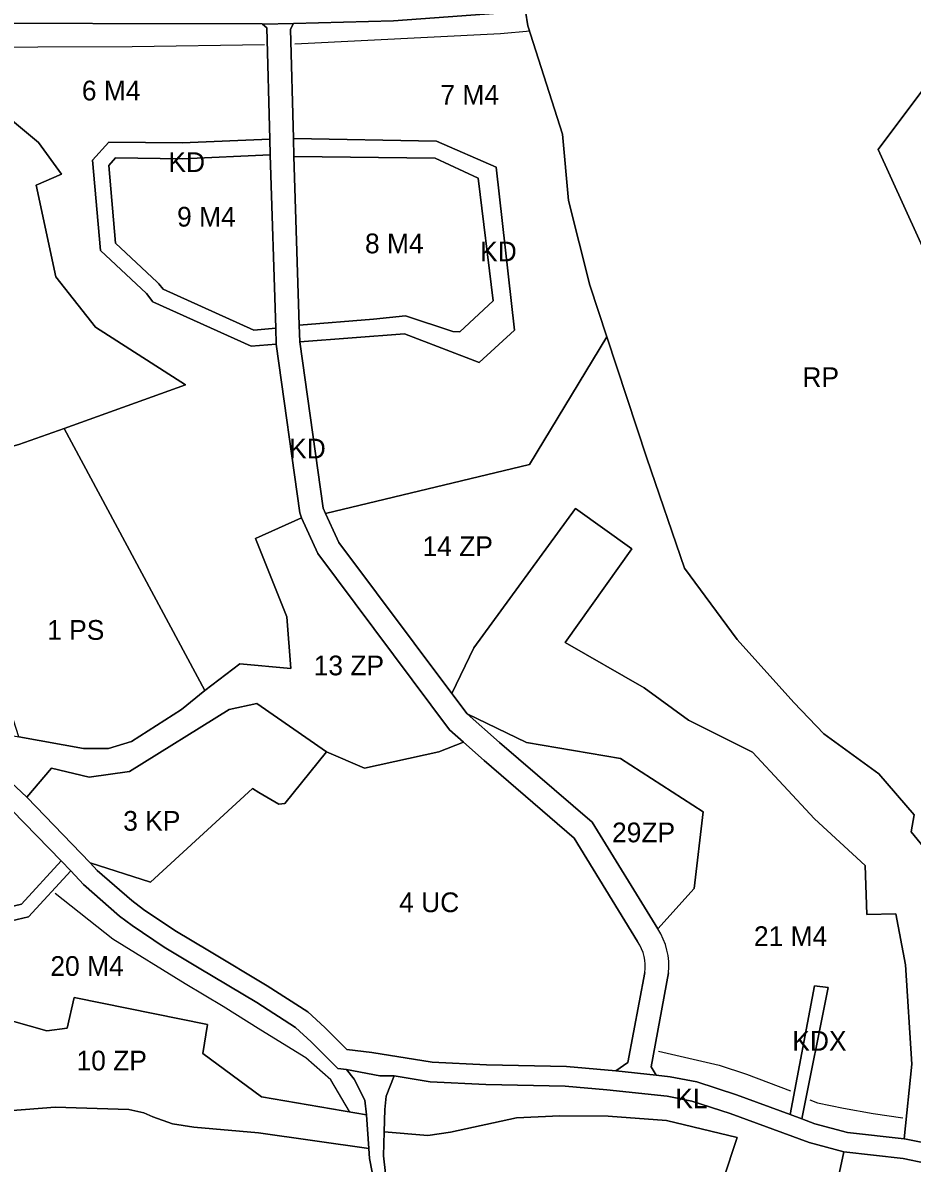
# Model space of a CAD drawing. Extents: x 7437831 to 7440315, y 5545798 to 5547888.
# Drawn here: x 7438934 to 7439385, y 5546989 to 5547567 of the extents above; entities that cross this region are included whole.
import ezdxf

# ---------------------------------------------------------------- set-up
doc = ezdxf.new("R2010")
doc.units = 0
for name, color, linetype in [('linie_rozgraniczajace', 7, 'Continuous'), ('linie_zabudowy_nieprzekraczalne', 7, 'Continuous'), ('oznaczenia_przeznaczen', 7, 'Continuous')]:
    doc.layers.add(name, color=color, linetype=linetype)

msp = doc.modelspace()

# ---------------------------------------------------------------- linework, layer by layer
at = {"layer": 'linie_rozgraniczajace'}
for points in [[(7439380.63, 5547586.73), (7439395.54, 5547573.5), (7439398.38, 5547559.18), (7439402.31, 5547543.75), (7439391.54, 5547533.89), (7439367.76, 5547502.29), (7439407.73, 5547414.82), (7439556.07, 5547232.92), (7439403.12, 5547142.44), (7439397.35, 5547140.99), (7439384.59, 5547156.64), (7439386.01, 5547165.4), (7439368.08, 5547186.09), (7439340.2, 5547206.42), (7439325.09, 5547222.17), (7439296.32, 5547254.08), (7439269.71, 5547290.21), (7439250.62, 5547346.08), (7439230.35, 5547407.55), (7439221.74, 5547433.66), (7439210.84, 5547476.54), (7439207.87, 5547510.17), (7439190.23, 5547565.03), (7439189.02, 5547572.47)], [(7439189.02, 5547572.47), (7439190.23, 5547565.03), (7439207.87, 5547510.17), (7439210.84, 5547476.54), (7439221.74, 5547433.66), (7439230.35, 5547407.55), (7439191.09, 5547342.82), (7439087.77, 5547317.91), (7439086.54, 5547320.63), (7439074.71, 5547404.92), (7439127.76, 5547409.05), (7439165.53, 5547394.42), (7439183.56, 5547410.93), (7439174.29, 5547493.48), (7439143.9, 5547506.62), (7439071.47, 5547507.9), (7439070.05, 5547563.26), (7439071.56, 5547566.23), (7439122.23, 5547567.49)], [(7438828.96, 5547566.29), (7438858.2, 5547566.45), (7438883.67, 5547566.33), (7438889.93, 5547556.37), (7438911.91, 5547531.01), (7438942.2, 5547505.98), (7438953.96, 5547489.8), (7438941.06, 5547484.22), (7438951.02, 5547437.82), (7438971.24, 5547412.38), (7439016.84, 5547383.23), (7438955.2, 5547361.08), (7438932.28, 5547352.94), (7438898.23, 5547343.32), (7438865.97, 5547445.48), (7438855.72, 5547499.1), (7438851.23, 5547513.66), (7438841.19, 5547535.01), (7438823.53, 5547527.36), (7438809.33, 5547551.21), (7438805.74, 5547563.28), (7438810.97, 5547564.3), (7438816.19, 5547565.31)], [(7439402.31, 5547543.75), (7439404.34, 5547535.78), (7439410.65, 5547514.06), (7439420.51, 5547489.6), (7439431.75, 5547471.05), (7439450.29, 5547445.41), (7439476.68, 5547412.41), (7439521.84, 5547350.29), (7439537.42, 5547327.35), (7439572.92, 5547278.45), (7439587.97, 5547258.66), (7439592.45, 5547251.78), (7439556.07, 5547232.92), (7439407.73, 5547414.82), (7439367.76, 5547502.29), (7439391.54, 5547533.89)], [(7439062.76, 5547403.81), (7439050.03, 5547402.66), (7439000.29, 5547425.19), (7438996.99, 5547429.39), (7438973.64, 5547451.23), (7438969.66, 5547497.02), (7438977.84, 5547506.11), (7439015.15, 5547505.71), (7439059.47, 5547507.6), (7439059.73, 5547499.6), (7439015.27, 5547497.71), (7438981.37, 5547498.07), (7438977.93, 5547494.25), (7438981.34, 5547454.97), (7439002.45, 5547435.23), (7439003.28, 5547434.33), (7439005.37, 5547431.67), (7439051.41, 5547410.81), (7439062.51, 5547411.8)], [(7439071.47, 5547507.9), (7439143.9, 5547506.62), (7439174.29, 5547493.48), (7439183.56, 5547410.93), (7439165.53, 5547394.42), (7439127.76, 5547409.05), (7439074.71, 5547404.92), (7439074.45, 5547413.34), (7439112.1, 5547416.37), (7439128.21, 5547418.04), (7439152.32, 5547410.11), (7439155.72, 5547409.99), (7439172.76, 5547425.7), (7439165.09, 5547487.89), (7439143.32, 5547497.95), (7439071.75, 5547498.86)], [(7439062.51, 5547411.8), (7439051.41, 5547410.81), (7439005.37, 5547431.67), (7439003.28, 5547434.33), (7439002.45, 5547435.23), (7438981.34, 5547454.97), (7438977.93, 5547494.25), (7438981.37, 5547498.07), (7439015.27, 5547497.71), (7439059.73, 5547499.6)], [(7439071.75, 5547498.86), (7439143.32, 5547497.95), (7439165.09, 5547487.89), (7439172.76, 5547425.7), (7439155.72, 5547409.99), (7439152.32, 5547410.11), (7439128.21, 5547418.04), (7439112.1, 5547416.37), (7439074.45, 5547413.34)], [(7438955.2, 5547361.08), (7439026.61, 5547228.25), (7439014.66, 5547218.74), (7438989.33, 5547202.5), (7438977.77, 5547198.98), (7438965.14, 5547198.94), (7438932.24, 5547204.92), (7438888.7, 5547340.63), (7438898.23, 5547343.32), (7438932.28, 5547352.94)], [(7439075.64, 5547315.72), (7439083.79, 5547297.7), (7439150.54, 5547208.32), (7439157.59, 5547202.13), (7439145.18, 5547197.27), (7439107.47, 5547188.91), (7439088.31, 5547197.19), (7439052.98, 5547221.74), (7439038.94, 5547218.77), (7438988.47, 5547187.22), (7438967.95, 5547184.39), (7438948.84, 5547188.98), (7438936.39, 5547174.36), (7438896.31, 5547211.65), (7438932.24, 5547204.92), (7438965.14, 5547198.94), (7438977.77, 5547198.98), (7438989.33, 5547202.5), (7439014.66, 5547218.74), (7439026.61, 5547228.25), (7439044.3, 5547241.89), (7439070.18, 5547239.54), (7439068.06, 5547265.64), (7439052.3, 5547305.33)], [(7438809.04, 5547223.28), (7438841.11, 5547194.03), (7438847.73, 5547185.6), (7438883.2, 5547212.78), (7438893.1, 5547200.63), (7438912.87, 5547182.74), (7438922.54, 5547173.99), (7438953.8, 5547142.07), (7438933.7, 5547120.16), (7438915.71, 5547115.81), (7438884.23, 5547111.26), (7438805.66, 5547070.29), (7438746.38, 5547044.16), (7438704.39, 5547030.75), (7438652.23, 5547099.85), (7438735.45, 5547165.35), (7438790.4, 5547208.6)], [(7438936.39, 5547174.36), (7438948.84, 5547188.98), (7438967.95, 5547184.39), (7438988.47, 5547187.22), (7439038.94, 5547218.77), (7439052.98, 5547221.74), (7439088.31, 5547197.19), (7439067.17, 5547171.08), (7439064, 5547170.71), (7439053.99, 5547176.68), (7439050.68, 5547178.66), (7438998.97, 5547131.16), (7438968.45, 5547141.03)], [(7439159.47, 5547216.45), (7439189.56, 5547202.03), (7439237.18, 5547193.81), (7439279.09, 5547166.79), (7439274.62, 5547127.96), (7439256.06, 5547107.5), (7439222.82, 5547161.54), (7439175.92, 5547201.99)], [(7439323.23, 5547013.51), (7439335.61, 5547078.66), (7439342.39, 5547077.83), (7439329.17, 5547011.32)]]:
    msp.add_lwpolyline(points, close=True, dxfattribs=at)
for points in [[(7439189.02, 5547572.47), (7439122.23, 5547567.49), (7439071.56, 5547566.23)], [(7439055.78, 5547565.86), (7439055.68, 5547565.95), (7438883.67, 5547566.33)], [(7438883.67, 5547566.33), (7439055.68, 5547565.95), (7439055.78, 5547565.86), (7439058.03, 5547563.99), (7439059.47, 5547507.6), (7439015.15, 5547505.71), (7438977.84, 5547506.11), (7438969.66, 5547497.02), (7438973.64, 5547451.23), (7438996.99, 5547429.39), (7439000.29, 5547425.19), (7439050.03, 5547402.66), (7439062.76, 5547403.81), (7439074.75, 5547318.29), (7439075.64, 5547315.72), (7439052.3, 5547305.33), (7439068.06, 5547265.64), (7439070.18, 5547239.54), (7439044.3, 5547241.89), (7439026.61, 5547228.25), (7438955.2, 5547361.08), (7439016.84, 5547383.23), (7438971.24, 5547412.38), (7438951.02, 5547437.82), (7438941.06, 5547484.22), (7438953.96, 5547489.8), (7438942.2, 5547505.98), (7438911.91, 5547531.01)], [(7439071.56, 5547566.23), (7439055.78, 5547565.86)], [(7439055.78, 5547565.86), (7439071.56, 5547566.23), (7439070.05, 5547563.26)], [(7439059.47, 5547507.6), (7439058.03, 5547563.99), (7439055.78, 5547565.86)], [(7439070.05, 5547563.26), (7439071.47, 5547507.9), (7439071.75, 5547498.86), (7439074.45, 5547413.34), (7439074.71, 5547404.92), (7439086.54, 5547320.63), (7439087.77, 5547317.91)], [(7439059.73, 5547499.6), (7439059.47, 5547507.6)], [(7439062.51, 5547411.8), (7439059.73, 5547499.6)], [(7439062.76, 5547403.81), (7439062.51, 5547411.8)], [(7439393.87, 5546998.67), (7439382.07, 5547001.08), (7439381.03, 5547001.2), (7439384.83, 5547039.06), (7439381.68, 5547089.27), (7439376.83, 5547115.26), (7439362.11, 5547114.77), (7439361.24, 5547139.74), (7439335.55, 5547163.34), (7439304.11, 5547197.02), (7439271.63, 5547213.34), (7439249.2, 5547229.62), (7439209.21, 5547252.55), (7439242.97, 5547300.1), (7439214.5, 5547320.47), (7439162.9, 5547249.87), (7439151.74, 5547226.79), (7439094.56, 5547303.33), (7439093.56, 5547305.16), (7439087.77, 5547317.91), (7439191.09, 5547342.82), (7439230.35, 5547407.55), (7439250.62, 5547346.08), (7439269.71, 5547290.21), (7439296.32, 5547254.08), (7439325.09, 5547222.17), (7439340.2, 5547206.42), (7439368.08, 5547186.09), (7439386.01, 5547165.4), (7439384.59, 5547156.64), (7439397.35, 5547140.99)], [(7439083.79, 5547297.7), (7439075.64, 5547315.72), (7439074.75, 5547318.29), (7439062.76, 5547403.81)], [(7439087.77, 5547317.91), (7439093.56, 5547305.16)], [(7439151.74, 5547226.79), (7439162.9, 5547249.87), (7439214.5, 5547320.47), (7439242.97, 5547300.1), (7439209.21, 5547252.55), (7439249.2, 5547229.62), (7439271.63, 5547213.34), (7439304.11, 5547197.02), (7439335.55, 5547163.34), (7439361.24, 5547139.74), (7439362.11, 5547114.77), (7439376.83, 5547115.26), (7439381.68, 5547089.27), (7439384.83, 5547039.06), (7439381.03, 5547001.2), (7439352.25, 5547004.45), (7439335.79, 5547008.87), (7439329.17, 5547011.32), (7439342.39, 5547077.83), (7439335.61, 5547078.66), (7439323.23, 5547013.51)], [(7439093.56, 5547305.16), (7439094.56, 5547303.33), (7439151.74, 5547226.79), (7439159.47, 5547216.45), (7439175.92, 5547201.99), (7439222.82, 5547161.54), (7439256.06, 5547107.5)], [(7439157.59, 5547202.13), (7439150.54, 5547208.32), (7439083.79, 5547297.7)], [(7439159.47, 5547216.45), (7439151.74, 5547226.79)], [(7439256.06, 5547107.5), (7439274.62, 5547127.96), (7439279.09, 5547166.79), (7439237.18, 5547193.81), (7439189.56, 5547202.03), (7439159.47, 5547216.45)], [(7438896.31, 5547211.65), (7438936.39, 5547174.36), (7438968.45, 5547141.03), (7438972.06, 5547137.15), (7438989.55, 5547121.86), (7438995.53, 5547117.4), (7439011.31, 5547106.7), (7439028.89, 5547096.29), (7439058.19, 5547078.79), (7439078.73, 5547065.47), (7439087.3, 5547057.66), (7439098.57, 5547046.41), (7439111.22, 5547044.95), (7439141.81, 5547040.11), (7439169.29, 5547038.7), (7439209.79, 5547037.88), (7439234.79, 5547035.73), (7439255.34, 5547033.45), (7439262.44, 5547032.69), (7439275.95, 5547030.01), (7439296.05, 5547023.53), (7439323.23, 5547013.51), (7439329.17, 5547011.32), (7439335.79, 5547008.87), (7439352.25, 5547004.45), (7439381.03, 5547001.2), (7439382.07, 5547001.08), (7439393.87, 5546998.67)], [(7439088.31, 5547197.19), (7439107.47, 5547188.91), (7439145.18, 5547197.27), (7439157.59, 5547202.13)], [(7439168.09, 5547192.91), (7439157.59, 5547202.13)], [(7439157.59, 5547202.13), (7439168.09, 5547192.91), (7439213.69, 5547153.57), (7439245.9, 5547101.1)], [(7439067.17, 5547171.08), (7439088.31, 5547197.19)], [(7439245.9, 5547101.1), (7439213.69, 5547153.57), (7439168.09, 5547192.91)], [(7439122.44, 5547033.05), (7439115.22, 5547033.09), (7439098.29, 5547036.37), (7439093.96, 5547036.87), (7439080.4, 5547050.42), (7439072.6, 5547057.52), (7439052.9, 5547070.3), (7439023.78, 5547087.7), (7439005.95, 5547098.26), (7438989.74, 5547109.25), (7438983.26, 5547114.08), (7438965.09, 5547129.96), (7438958.59, 5547136.94), (7438953.8, 5547142.07), (7438922.54, 5547173.99)], [(7438968.45, 5547141.03), (7438998.97, 5547131.16), (7439050.68, 5547178.66), (7439053.99, 5547176.68)], [(7439053.99, 5547176.68), (7439064, 5547170.71)], [(7439064, 5547170.71), (7439067.17, 5547171.08)], [(7438652.23, 5547099.85), (7438704.39, 5547030.75), (7438746.38, 5547044.16), (7438805.66, 5547070.29), (7438884.23, 5547111.26), (7438915.71, 5547115.81), (7438933.7, 5547120.16), (7438953.8, 5547142.07), (7438958.59, 5547136.94), (7438937.15, 5547113.6), (7438917, 5547108.92), (7438885.26, 5547103.9), (7438820.52, 5547070.25), (7438808.31, 5547063.92), (7438785.09, 5547053.09), (7438754.01, 5547039.54), (7438745.95, 5547035.56), (7438745.69, 5547027.85), (7438750.73, 5547018.27), (7438759.29, 5547000.75), (7438776.27, 5546970.26)], [(7439028.89, 5547096.29), (7439011.31, 5547106.7), (7438995.53, 5547117.4), (7438989.55, 5547121.86), (7438972.06, 5547137.15), (7438968.45, 5547141.03)], [(7438917, 5547108.92), (7438937.15, 5547113.6), (7438958.59, 5547136.94), (7438965.09, 5547129.96), (7438983.26, 5547114.08), (7438989.74, 5547109.25), (7439005.95, 5547098.26), (7439023.78, 5547087.7), (7439052.9, 5547070.3), (7439072.6, 5547057.52), (7439080.4, 5547050.42), (7439093.96, 5547036.87), (7439098.29, 5547036.37), (7439102.27, 5547031.4), (7439107.64, 5547020.79), (7439108.48, 5547013.32), (7439055.34, 5547022.44), (7439025.55, 5547044.39), (7439027.89, 5547059.08), (7438960.36, 5547072.81), (7438956.82, 5547057.3), (7438946.48, 5547055.89), (7438918.34, 5547063.78)], [(7439087.3, 5547057.66), (7439078.73, 5547065.47), (7439058.19, 5547078.79), (7439028.89, 5547096.29)], [(7439234.79, 5547035.73), (7439240.9, 5547039.8), (7439249.58, 5547085.51)], [(7439249.58, 5547085.51), (7439240.9, 5547039.8), (7439234.79, 5547035.73)], [(7439261.62, 5547085.23), (7439252.8, 5547037.74), (7439255.34, 5547033.45), (7439234.79, 5547035.73)], [(7439323.23, 5547013.51), (7439296.05, 5547023.53), (7439275.95, 5547030.01), (7439262.44, 5547032.69), (7439255.34, 5547033.45), (7439252.8, 5547037.74), (7439261.62, 5547085.23)], [(7438918.34, 5547063.78), (7438946.48, 5547055.89), (7438956.82, 5547057.3), (7438960.36, 5547072.81), (7439027.89, 5547059.08), (7439025.55, 5547044.39), (7439055.34, 5547022.44), (7439108.48, 5547013.32), (7439109.68, 5546996.29), (7439053.79, 5547004.19), (7439020.96, 5547007.18), (7439010.11, 5547008.78), (7439000.18, 5547012.43), (7438995.61, 5547014.35), (7438988, 5547016.02), (7438950.69, 5547017.22), (7438918.29, 5547014.78)], [(7439234.79, 5547035.73), (7439209.79, 5547037.88), (7439169.29, 5547038.7), (7439141.81, 5547040.11), (7439111.22, 5547044.95), (7439098.57, 5547046.41), (7439087.3, 5547057.66)], [(7439112.9, 5546976.52), (7439110.04, 5546991.19), (7439109.68, 5546996.29), (7439108.48, 5547013.32), (7439107.64, 5547020.79), (7439102.27, 5547031.4), (7439098.29, 5547036.37), (7439115.22, 5547033.09), (7439122.44, 5547033.05), (7439118.53, 5547022.79), (7439117.82, 5547016.13), (7439117.45, 5547004.79), (7439117.06, 5546992.55), (7439119.3, 5546973.15)], [(7439289.28, 5546980.4), (7439296.42, 5547001.93), (7439260.46, 5547010.5), (7439230.95, 5547012.75), (7439206.47, 5547012.79), (7439184.58, 5547011.89), (7439151.05, 5547004.59), (7439139.66, 5547002.89), (7439117.45, 5547004.79), (7439117.82, 5547016.13), (7439118.53, 5547022.79), (7439122.44, 5547033.05), (7439140.77, 5547030.15), (7439168.94, 5547028.71), (7439209.22, 5547027.89), (7439230.27, 5547026.08), (7439260.93, 5547022.79), (7439273.43, 5547020.32), (7439292.79, 5547014.08), (7439332.76, 5546999.33), (7439350.33, 5546994.61), (7439343.28, 5546961.3)], [(7439391.83, 5546988.88), (7439380.51, 5546991.19), (7439350.33, 5546994.61), (7439332.76, 5546999.33), (7439292.79, 5547014.08), (7439273.43, 5547020.32), (7439260.93, 5547022.79), (7439230.27, 5547026.08), (7439209.22, 5547027.89), (7439168.94, 5547028.71), (7439140.77, 5547030.15), (7439122.44, 5547033.05)], [(7438918.29, 5547014.78), (7438950.69, 5547017.22), (7438988, 5547016.02), (7438995.61, 5547014.35), (7439000.18, 5547012.43), (7439010.11, 5547008.78), (7439020.96, 5547007.18), (7439053.79, 5547004.19), (7439109.68, 5546996.29), (7439110.04, 5546991.19), (7439112.9, 5546976.52)], [(7439119.3, 5546973.15), (7439117.06, 5546992.55), (7439117.45, 5547004.79), (7439139.66, 5547002.89), (7439151.05, 5547004.59), (7439184.58, 5547011.89), (7439206.47, 5547012.79), (7439230.95, 5547012.75), (7439260.46, 5547010.5), (7439296.42, 5547001.93), (7439289.28, 5546980.4)], [(7439343.28, 5546961.3), (7439350.33, 5546994.61), (7439380.51, 5546991.19), (7439391.83, 5546988.88)]]:
    msp.add_lwpolyline(points, dxfattribs=at)
for centre, radius, start, end in [((7439227.6964, 5547088.5896), 34.0896, 354.3442219, 33.6919406), ((7439227.6964, 5547088.5896), 34.0896, 354.3442219, 33.6919406), ((7439227.6623, 5547088.5657), 22.1297, 352.0631907, 34.4997734), ((7439227.6623, 5547088.5657), 22.1297, 352.0631907, 34.4997734)]:
    msp.add_arc(centre, radius, start, end, dxfattribs=at)
at = {"layer": 'linie_zabudowy_nieprzekraczalne'}
for points in [[(7439191.41, 5547562.36), (7439176.49, 5547560.96), (7439072.24, 5547555.76)], [(7439056.82, 5547555.41), (7438989.74, 5547554.31), (7438893.98, 5547553.98)], [(7439099.96, 5547015.11), (7439090.35, 5547031.07), (7439077.69, 5547042.16), (7439054.92, 5547056.28), (7439035.91, 5547068.23), (7439016.53, 5547079.72), (7438980.01, 5547102.39), (7438950.71, 5547125.41)], [(7439256.47, 5547045.69), (7439287.26, 5547038.46), (7439301.07, 5547033.99), (7439323.46, 5547025.45)], [(7439333.12, 5547020.97), (7439337.04, 5547019.48), (7439350.28, 5547016.66), (7439365.34, 5547013.99), (7439380.31, 5547011.91)]]:
    msp.add_lwpolyline(points, dxfattribs=at)

# ---------------------------------------------------------------- texts
at = {"layer": 'oznaczenia_przeznaczen'}
for s, p in [('6 M4', (7438964.255, 5547527.24)), ('7 M4', (7439145.945, 5547525.12)), ('KD', (7439008.1027, 5547490.96)), ('9 M4', (7439012.515, 5547463.31)), ('8 M4', (7439107.735, 5547449.78)), ('KD', (7439166.0727, 5547445.71)), ('RP', (7439329.4032, 5547382.02)), ('KD', (7439069.2927, 5547345.88)), ('14 ZP', (7439136.8883, 5547296.39)), ('1 PS', (7438946.6663, 5547253.99)), ('13 ZP', (7439081.7183, 5547236)), ('3 KP', (7438985.1953, 5547157.28)), ('29ZP', (7439232.9406, 5547151.42)), ('4 UC', (7439125.0396, 5547116.02)), ('21 M4', (7439304.8405, 5547098.89)), ('20 M4', (7438948.2905, 5547083.74)), ('KDX', (7439324.2943, 5547045.83)), ('10 ZP', (7438961.5383, 5547035.85)), ('KL', (7439265.0098, 5547016.69))]:
    msp.add_text(s, height=10, dxfattribs=at).set_placement(p)

doc.saveas('drawing.dxf')
